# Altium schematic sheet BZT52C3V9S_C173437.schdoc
size 127 x 101 mm
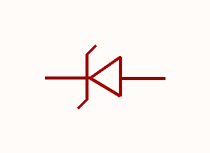
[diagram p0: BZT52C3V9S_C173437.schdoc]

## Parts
D?  bzt52c3v9s_c173437  [SOD-323_L1.8-W1.3-LS2.5-RD]  (value not drawn)

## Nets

Not connected (* = marked no-connect by the designer): D? 1(K) 2(A)

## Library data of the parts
D? = bzt52c3v9s_c173437: 二极管配置:1个独立式;稳压值(标称值):3.9V;稳压值(范围):3.7V~4.1V;耗散功率(Pd):200mW;; Manufacturer: MDD(辰达半导体); AddInBom: yes; ModelId: db63db13d9e342eb939127d413d6200b; ModelTransform: 104.3305,51.181,0,0,0,0,0,-0.004,0; Diode Configuration: 1个独立式; Zener Voltage(Nom): 3.9V; Reverse Leakage Current (Ir): 5uA@1V; Pd - Power Dissipation: 200mW; Impedance(Zzt): 130Ω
